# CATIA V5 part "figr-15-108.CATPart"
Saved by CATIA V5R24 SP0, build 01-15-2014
Part number: Part1
Bounding box of the stored display mesh (mm): x -60.955 to 60.955, y -33.748 to 33.748, z 0 to 6.052
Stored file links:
  D:\KAVITA\CATIA V5-6R2014 Project_ Kavita\CATIA V5-6R2014_partfiles\Partfiles\c15_catia_v5-6r2014_prt\figr-15-108.CATPart
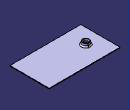
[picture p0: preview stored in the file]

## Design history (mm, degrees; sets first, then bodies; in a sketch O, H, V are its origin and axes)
SheetMetalParameters1: Thickness 1, BendRadius 5, KFactor 0.5 {= log(min(100,max(20*SheetMetalParameters1.BendRadius,SheetMetalParameters1.Thickness)/SheetMetalParameters1.Thickness))/log(100)/2}, ReliefRadialLength 1, ReliefAxialLength 2, MinimumBendRadius 0
Body1 (main body)
  Sketch1 on xy-plane, origin (0, 0, 0), H (1, 0, 0), V (0, 1, 0)
    line L1 (60.9549, 33.7477) -> (60.9549, -33.7477)
    line L2 (60.9549, -33.7477) -> (-60.9549, -33.7477)
    line L3 (-60.9549, -33.7477) -> (-60.9549, 33.7477)
    line L4 (-60.9549, 33.7477) -> (60.9549, 33.7477)
    vertical: L1 V, L3 V
    horizontal: L2 H, L4 H
    equidistance: L1 L3 O, L2 L4 O
  Wall1: Thickness 1, Profile Sketch1
  Sketch2 on face of Wall1, origin (0, 0, 1), H (1, 0, 0), V (0, 1, 0)
    point P1 (-35.8601, 0)
    coincidence: P1 H
  Sketch3 on face of Wall1, origin (-35.8601, 0, 1), H (1, 0, 0), V (0, 1, 0)
    point P1 (0, 0)
    reference projected point E1 (0, 0) from Sketch2.P1
    coincidence: E1 P1
  d_Stamp1: KFacteur 0.5 {= SheetMetalParameters1.KFactor}, Stamp_FilletRadius 2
